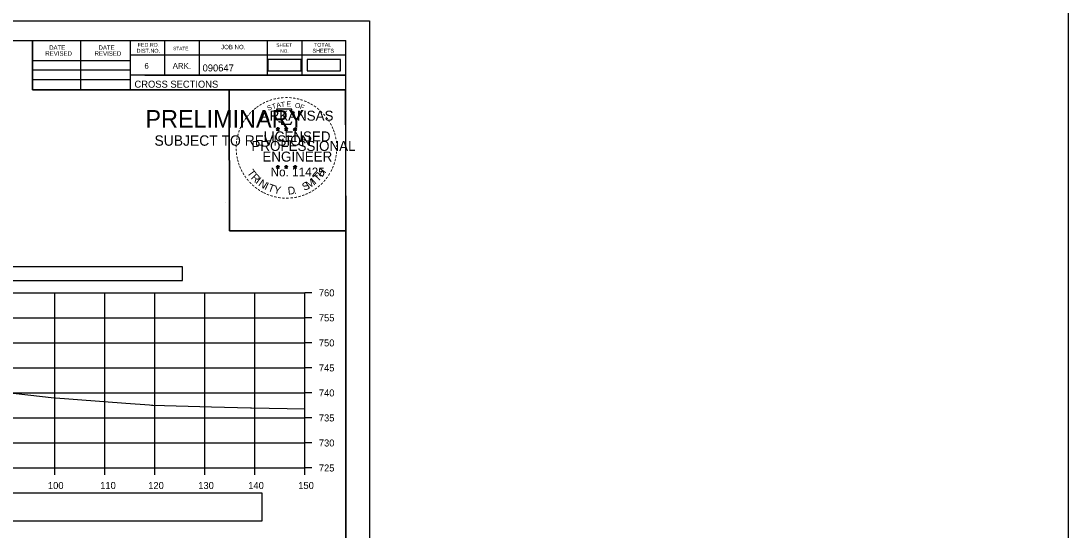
# Model space of a CAD drawing. Extents: x 1202951 to 1376887, y 378065 to 728038.
# Drawn here: x 1376677.9 to 1376887.3, y 378519.4 to 378621.2 of the extents above; entities that cross this region are included whole.
import ezdxf

# ---------------------------------------------------------------- set-up
doc = ezdxf.new("R2010")
doc.units = 0
for name, color, linetype in [('Default', 7, 'Continuous'), ('R_Alt Surface', 7, 'Continuous'), ('R_Axis', 7, 'Continuous'), ('R_Axis Annot', 7, 'Continuous'), ('R_Border', 7, 'Continuous'), ('R_Border PE', 7, 'Continuous'), ('R_Border Prem', 7, 'Continuous'), ('R_Exist Surface', 7, 'Continuous'), ('R_Grid', 7, 'Continuous'), ('R_No Plot', 7, 'Continuous')]:
    doc.layers.add(name, color=color, linetype=linetype)

msp = doc.modelspace()

# ---------------------------------------------------------------- linework, layer by layer
at = {"layer": 'Default'}
msp.add_lwpolyline([(1376735.11, 378611.18), (1376741.79, 378611.18), (1376741.79, 378613.49), (1376735.11, 378613.49)], close=True, dxfattribs=at)
at = {"layer": 'R_Alt Surface'}
for points in [[(1376727.24, 378611.18), (1376733.92, 378611.18), (1376733.92, 378613.49), (1376727.24, 378613.49)], [(1376434.67, 378569.32), (1376710.2, 378569.32), (1376710.2, 378572.02), (1376434.67, 378572.02)], [(1376615.43, 378521.29), (1376726.14, 378521.29), (1376726.14, 378526.82), (1376615.43, 378526.82)]]:
    msp.add_lwpolyline(points, close=True, dxfattribs=at)
at = {"layer": 'R_Axis'}
for p, q in [((1376734.67, 378531.82), (1376734.67, 378566.82)), ((1376736.07, 378566.82), (1376734.67, 378566.82)), ((1376736.07, 378561.82), (1376734.67, 378561.82)), ((1376736.07, 378556.82), (1376734.67, 378556.82)), ((1376736.07, 378551.82), (1376734.67, 378551.82)), ((1376736.07, 378546.82), (1376734.67, 378546.82)), ((1376736.07, 378541.82), (1376734.67, 378541.82)), ((1376736.07, 378536.82), (1376734.67, 378536.82)), ((1376434.67, 378531.82), (1376734.67, 378531.82)), ((1376684.67, 378530.42), (1376684.67, 378531.82)), ((1376694.67, 378530.42), (1376694.67, 378531.82)), ((1376704.67, 378530.42), (1376704.67, 378531.82)), ((1376714.67, 378530.42), (1376714.67, 378531.82)), ((1376724.67, 378530.42), (1376724.67, 378531.82)), ((1376734.67, 378530.42), (1376734.67, 378531.82)), ((1376736.07, 378531.82), (1376734.67, 378531.82))]:
    msp.add_line(p, q, dxfattribs=at)
at = {"layer": 'R_Border'}
for p, q in [((1376426.67, 378617.28), (1376742.85, 378617.28)), ((1376680.21, 378607.4), (1376680.21, 378617.28)), ((1376689.89, 378607.4), (1376689.89, 378617.28)), ((1376699.75, 378617.28), (1376699.75, 378607.4)), ((1376706.59, 378617.28), (1376706.59, 378610.34)), ((1376713.53, 378617.28), (1376713.53, 378610.34)), ((1376727.11, 378617.28), (1376727.11, 378610.34)), ((1376734.05, 378617.28), (1376734.05, 378610.34)), ((1376742.85, 378411.82), (1376742.85, 378617.28)), ((1376742.85, 378614.34), (1376699.75, 378614.34)), ((1376742.85, 378614.36), (1376742.85, 378614.36)), ((1376680.21, 378613.26), (1376699.75, 378613.26)), ((1376680.21, 378611.4), (1376699.75, 378611.4)), ((1376680.21, 378609.46), (1376699.75, 378609.46)), ((1376742.85, 378610.34), (1376699.75, 378610.34)), ((1376702.71, 378610.34), (1376742.85, 378610.34)), ((1376742.85, 378607.4), (1376680.21, 378607.4))]:
    msp.add_line(p, q, dxfattribs=at)
at = {"layer": 'R_Border PE'}
for p, q in [((1376728.94, 378599.65), (1376729.28, 378599.54)), ((1376728.94, 378599.65), (1376729.19, 378599.61)), ((1376728.94, 378599.65), (1376729.17, 378599.53)), ((1376729.07, 378599.24), (1376729.28, 378599.54)), ((1376729.07, 378599.24), (1376729.19, 378599.49)), ((1376729.07, 378599.24), (1376729.28, 378599.46)), ((1376729.28, 378599.91), (1376729.24, 378599.65)), ((1376729.28, 378599.54), (1376729.28, 378599.91)), ((1376729.28, 378599.91), (1376729.33, 378599.66)), ((1376729.63, 378599.65), (1376729.28, 378599.54)), ((1376729.5, 378599.24), (1376729.28, 378599.54)), ((1376729.5, 378599.24), (1376729.28, 378599.46)), ((1376729.63, 378599.65), (1376729.35, 378599.6)), ((1376729.5, 378599.24), (1376729.36, 378599.53)), ((1376729.63, 378599.65), (1376729.43, 378599.55)), ((1376730.61, 378599.65), (1376730.95, 378599.54)), ((1376730.61, 378599.65), (1376730.86, 378599.61)), ((1376730.61, 378599.65), (1376730.84, 378599.53)), ((1376730.74, 378599.24), (1376730.95, 378599.54)), ((1376730.74, 378599.24), (1376730.86, 378599.49)), ((1376730.74, 378599.24), (1376730.95, 378599.46)), ((1376730.95, 378599.91), (1376730.91, 378599.65)), ((1376730.95, 378599.54), (1376730.95, 378599.91)), ((1376730.95, 378599.91), (1376731, 378599.66)), ((1376731.3, 378599.65), (1376730.95, 378599.54)), ((1376731.17, 378599.24), (1376730.95, 378599.54)), ((1376731.17, 378599.24), (1376730.95, 378599.46)), ((1376731.3, 378599.65), (1376731.02, 378599.6)), ((1376731.17, 378599.24), (1376731.03, 378599.53)), ((1376731.3, 378599.65), (1376731.1, 378599.55)), ((1376732.37, 378599.64), (1376732.72, 378599.53)), ((1376732.37, 378599.64), (1376732.62, 378599.59)), ((1376732.37, 378599.64), (1376732.61, 378599.52)), ((1376732.5, 378599.23), (1376732.72, 378599.53)), ((1376732.5, 378599.23), (1376732.63, 378599.48)), ((1376732.5, 378599.23), (1376732.72, 378599.45)), ((1376732.72, 378599.89), (1376732.68, 378599.64)), ((1376732.72, 378599.53), (1376732.72, 378599.89)), ((1376732.72, 378599.89), (1376732.77, 378599.64)), ((1376733.07, 378599.64), (1376732.72, 378599.53)), ((1376732.93, 378599.23), (1376732.72, 378599.53)), ((1376732.93, 378599.23), (1376732.72, 378599.45)), ((1376733.07, 378599.64), (1376732.78, 378599.59)), ((1376732.93, 378599.23), (1376732.79, 378599.52)), ((1376733.07, 378599.64), (1376732.86, 378599.54)), ((1376728.93, 378592.08), (1376729.28, 378591.97)), ((1376728.93, 378592.08), (1376729.18, 378592.03)), ((1376728.93, 378592.08), (1376729.17, 378591.96)), ((1376729.06, 378591.67), (1376729.28, 378591.97)), ((1376729.06, 378591.67), (1376729.19, 378591.91)), ((1376729.06, 378591.67), (1376729.28, 378591.89)), ((1376729.28, 378592.33), (1376729.24, 378592.08)), ((1376729.28, 378591.97), (1376729.28, 378592.33)), ((1376729.28, 378592.33), (1376729.33, 378592.08)), ((1376729.63, 378592.08), (1376729.28, 378591.97)), ((1376729.49, 378591.67), (1376729.28, 378591.97)), ((1376729.49, 378591.67), (1376729.28, 378591.88)), ((1376729.63, 378592.08), (1376729.34, 378592.03)), ((1376729.49, 378591.67), (1376729.36, 378591.96)), ((1376729.63, 378592.08), (1376729.42, 378591.98)), ((1376730.6, 378592.08), (1376730.95, 378591.97)), ((1376730.6, 378592.08), (1376730.85, 378592.03)), ((1376730.6, 378592.08), (1376730.84, 378591.96)), ((1376730.73, 378591.67), (1376730.95, 378591.97)), ((1376730.73, 378591.67), (1376730.86, 378591.91)), ((1376730.73, 378591.67), (1376730.95, 378591.89)), ((1376730.95, 378592.33), (1376730.91, 378592.08)), ((1376730.95, 378591.97), (1376730.95, 378592.33)), ((1376730.95, 378592.33), (1376731, 378592.08)), ((1376731.3, 378592.08), (1376730.95, 378591.97)), ((1376731.16, 378591.67), (1376730.95, 378591.97)), ((1376731.16, 378591.67), (1376730.95, 378591.88)), ((1376731.3, 378592.08), (1376731.01, 378592.03)), ((1376731.16, 378591.67), (1376731.03, 378591.96)), ((1376731.3, 378592.08), (1376731.09, 378591.98)), ((1376732.37, 378592.07), (1376732.72, 378591.96)), ((1376732.37, 378592.07), (1376732.62, 378592.02)), ((1376732.37, 378592.07), (1376732.6, 378591.95)), ((1376732.5, 378591.66), (1376732.72, 378591.96)), ((1376732.5, 378591.66), (1376732.63, 378591.9)), ((1376732.5, 378591.66), (1376732.71, 378591.88)), ((1376732.72, 378592.32), (1376732.68, 378592.07)), ((1376732.93, 378591.66), (1376732.71, 378591.87)), ((1376732.72, 378591.96), (1376732.72, 378592.32)), ((1376732.72, 378592.32), (1376732.77, 378592.07)), ((1376733.06, 378592.07), (1376732.72, 378591.96)), ((1376732.93, 378591.66), (1376732.72, 378591.96)), ((1376733.06, 378592.07), (1376732.78, 378592.02)), ((1376732.93, 378591.66), (1376732.79, 378591.95)), ((1376733.06, 378592.07), (1376732.86, 378591.97))]:
    msp.add_line(p, q, dxfattribs=at)
for points in [[(1376728.98, 378603.53), (1376729.25, 378602.7)], [(1376732.49, 378602.61), (1376732.63, 378602.89), (1376731.94, 378602.87), (1376732.09, 378603.53), (1376728.98, 378603.53)], [(1376729.47, 378601.11), (1376729.47, 378601.02), (1376730.03, 378601), (1376729.98, 378600.53), (1376731.85, 378600.53), (1376732.05, 378601.06)], [(1376729.28, 378599.91), (1376729.5, 378599.24), (1376728.94, 378599.65), (1376729.63, 378599.65), (1376729.07, 378599.24), (1376729.28, 378599.91)], [(1376730.95, 378599.91), (1376731.17, 378599.24), (1376730.61, 378599.65), (1376731.3, 378599.65), (1376730.74, 378599.24), (1376730.95, 378599.91)], [(1376732.72, 378599.89), (1376732.93, 378599.23), (1376732.37, 378599.64), (1376733.07, 378599.64), (1376732.5, 378599.23), (1376732.72, 378599.89)], [(1376729.28, 378592.33), (1376729.49, 378591.67), (1376728.93, 378592.08), (1376729.63, 378592.08), (1376729.06, 378591.67), (1376729.28, 378592.33)], [(1376730.95, 378592.33), (1376731.16, 378591.67), (1376730.6, 378592.08), (1376731.3, 378592.08), (1376730.73, 378591.67), (1376730.95, 378592.33)], [(1376732.72, 378592.32), (1376732.93, 378591.66), (1376732.37, 378592.07), (1376733.06, 378592.07), (1376732.5, 378591.66), (1376732.72, 378592.32)]]:
    msp.add_lwpolyline(points, dxfattribs=at)
for centre, radius in [((1376729.28, 378599.54), 0.172), ((1376729.28, 378599.54), 0.145), ((1376729.28, 378599.54), 0.116), ((1376729.28, 378599.54), 0.0991), ((1376729.28, 378599.54), 0.0747), ((1376729.28, 378599.54), 0.0495), ((1376729.28, 378599.54), 0.0296), ((1376730.95, 378599.54), 0.172), ((1376730.95, 378599.54), 0.145), ((1376730.95, 378599.54), 0.116), ((1376730.95, 378599.54), 0.0991), ((1376730.95, 378599.54), 0.0747), ((1376730.95, 378599.54), 0.0495), ((1376730.95, 378599.54), 0.0296), ((1376732.72, 378599.53), 0.172), ((1376732.72, 378599.53), 0.145), ((1376732.72, 378599.53), 0.116), ((1376732.72, 378599.53), 0.0991), ((1376732.72, 378599.53), 0.0747), ((1376732.72, 378599.53), 0.0495), ((1376732.72, 378599.53), 0.0296), ((1376729.28, 378591.97), 0.172), ((1376729.28, 378591.97), 0.145), ((1376729.28, 378591.97), 0.116), ((1376729.28, 378591.97), 0.0991), ((1376729.28, 378591.97), 0.0747), ((1376729.28, 378591.97), 0.0495), ((1376729.28, 378591.97), 0.0296), ((1376730.95, 378591.97), 0.172), ((1376730.95, 378591.97), 0.145), ((1376730.95, 378591.97), 0.116), ((1376730.95, 378591.97), 0.0991), ((1376730.95, 378591.97), 0.0747), ((1376730.95, 378591.97), 0.0495), ((1376730.95, 378591.97), 0.0296), ((1376732.72, 378591.96), 0.172), ((1376732.72, 378591.96), 0.145), ((1376732.72, 378591.96), 0.116), ((1376732.72, 378591.96), 0.0991), ((1376732.72, 378591.96), 0.0747), ((1376732.72, 378591.96), 0.0495), ((1376732.72, 378591.96), 0.0296)]:
    msp.add_circle(centre, radius, dxfattribs=at)
at = {"layer": 'R_Exist Surface'}
msp.add_lwpolyline([(1376663.94, 378548.16), (1376682.2, 378546.14), (1376683.97, 378545.91), (1376698.86, 378544.76), (1376703.59, 378544.41), (1376704, 378544.38), (1376704.27, 378544.37), (1376716.02, 378544.06), (1376723.79, 378543.85), (1376724.03, 378543.85), (1376734.67, 378543.65)], dxfattribs=at)
at = {"layer": 'R_Grid'}
for p, q in [((1376434.67, 378566.82), (1376734.67, 378566.82)), ((1376684.67, 378531.82), (1376684.67, 378566.82)), ((1376694.67, 378531.82), (1376694.67, 378566.82)), ((1376704.67, 378531.82), (1376704.67, 378566.82)), ((1376714.67, 378531.82), (1376714.67, 378566.82)), ((1376724.67, 378531.82), (1376724.67, 378566.82)), ((1376734.67, 378531.82), (1376734.67, 378566.82)), ((1376434.67, 378561.82), (1376734.67, 378561.82)), ((1376434.67, 378556.82), (1376734.67, 378556.82)), ((1376434.67, 378551.82), (1376734.67, 378551.82)), ((1376434.67, 378546.82), (1376734.67, 378546.82)), ((1376434.67, 378541.82), (1376734.67, 378541.82)), ((1376434.67, 378536.82), (1376734.67, 378536.82)), ((1376434.67, 378531.82), (1376734.67, 378531.82))]:
    msp.add_line(p, q, dxfattribs=at)
at = {"layer": 'R_No Plot'}
for p, q in [((1376414.27, 378621.17), (1376747.6, 378621.17)), ((1376718.89, 378584.94), (1376718.89, 378584.94))]:
    msp.add_line(p, q, dxfattribs=at)
for points in [[(1376303.24, 380162.87), (1376887.29, 380162.87), (1376887.29, 378065.39), (1376303.24, 378065.39)], [(1376414.26, 378621.17), (1376747.6, 378621.17), (1376747.6, 378407.83), (1376414.26, 378407.83)], [(1376660.59, 378617.28), (1376680.21, 378617.28), (1376680.21, 378607.4), (1376696.32, 378607.4), (1376719.52, 378607.4), (1376719.64, 378579.24), (1376742.85, 378579.24), (1376742.85, 378411.82), (1376426.67, 378411.82), (1376426.67, 378617.28)], [(1376719.52, 378607.4), (1376742.73, 378607.4), (1376742.85, 378579.24), (1376719.64, 378579.24)]]:
    msp.add_lwpolyline(points, close=True, dxfattribs=at)

# ---------------------------------------------------------------- texts
at = {"layer": 'R_Axis Annot'}
for s, p in [('760', (1376737.47, 378566.12)), ('755', (1376737.47, 378561.12)), ('750', (1376737.47, 378556.12)), ('745', (1376737.47, 378551.12)), ('740', (1376737.47, 378546.12)), ('735', (1376737.47, 378541.12)), ('730', (1376737.47, 378536.12)), ('725', (1376737.47, 378531.12)), ('100', (1376683.3, 378527.62)), ('110', (1376693.75, 378527.62)), ('120', (1376703.35, 378527.62)), ('130', (1376713.35, 378527.62)), ('140', (1376723.35, 378527.62)), ('150', (1376733.35, 378527.62))]:
    msp.add_text(s, height=1.4, dxfattribs=at).set_placement(p)
at = {"layer": 'R_Border'}
for s, height, p in [('DATE', 0.879, (1376683.55, 378615.41)), ('DATE', 0.879, (1376693.41, 378615.41)), ('DIST.NO.', 0.782, (1376701.03, 378614.82)), ('FED.RD.', 0.782, (1376701.23, 378616)), ('STATE', 0.684, (1376708.35, 378615.32)), ('JOB NO.', 0.879, (1376717.93, 378615.52)), ('SHEET', 0.684, (1376728.97, 378616)), ('NO.', 0.684, (1376729.75, 378614.82)), ('SHEETS', 0.782, (1376736.21, 378614.82)), ('TOTAL', 0.782, (1376736.49, 378616)), ('REVISED', 0.879, (1376682.77, 378614.23)), ('REVISED', 0.879, (1376692.63, 378614.23)), ('6', 1.17, (1376702.59, 378611.6)), ('ARK.', 1.172, (1376708.25, 378611.6)), ('090647', 1.4, (1376714.23, 378611.08)), ('CROSS SECTIONS', 1.4, (1376700.61, 378607.83))]:
    msp.add_text(s, height=height, rotation=360, dxfattribs=at).set_placement(p)
at = {"layer": 'R_Border PE'}
for s, height, rotation, p in [('-', 1.6, 28.7918, (1376726.46, 378604.07)), ('-', 1.6, 24.3072, (1376727.09, 378604.39)), ('-', 1.6, 19.1761, (1376727.72, 378604.66)), ('-', 1.6, 13.6301, (1376728.47, 378604.9)), ('-', 1.6, 10.2193, (1376729.15, 378605.06)), ('T', 1, 6.0228, (1376729.92, 378603.96)), ('-', 1.6, 5.8968, (1376729.88, 378605.17)), ('-', 1.6, 0.1862, (1376730.65, 378605.24)), ('E', 1, 0.8323, (1376731.03, 378604.07)), ('-', 1.6, 357.743, (1376731.38, 378605.23)), ('-', 1.6, 352.1617, (1376732.12, 378605.17)), ('-', 1.6, 347.2049, (1376732.84, 378605.06)), ('-', 1.6, 342.3362, (1376733.47, 378604.9)), ('-', 1.6, 337.8551, (1376734.21, 378604.68)), ('-', 1.6, 334.1211, (1376734.84, 378604.41)), ('-', 1.6, 48.423, (1376723.93, 378602.03)), ('-', 1.6, 42.9622, (1376724.37, 378602.51)), ('-', 1.6, 38.9507, (1376724.81, 378602.93)), ('-', 1.6, 36.2317, (1376725.28, 378603.31)), ('-', 1.6, 34.0636, (1376725.86, 378603.7)), ('ARKANSAS', 2, 360, (1376725.83, 378601.24)), ('S', 1, 21.594, (1376727.33, 378603.21)), ('T', 1, 16.4036, (1376728.25, 378603.54)), ('A', 1, 11.2132, (1376729.07, 378603.79)), ('O', 1, 350.4515, (1376732.63, 378603.86)), ('F', 1, 340.0707, (1376733.58, 378603.63)), ('-', 1.6, 329.6409, (1376735.42, 378604.13)), ('-', 1.6, 325.8627, (1376736.06, 378603.77)), ('-', 1.6, 320.5297, (1376736.67, 378603.34)), ('-', 1.6, 315.5786, (1376737.27, 378602.85)), ('-', 1.6, 58.0706, (1376722.78, 378600.45)), ('-', 1.6, 54.2325, (1376723.11, 378600.98)), ('-', 1.6, 50.6142, (1376723.52, 378601.55)), ('-', 1.6, 309.8797, (1376737.84, 378602.3)), ('-', 1.6, 306.6522, (1376738.37, 378601.7)), ('-', 1.4, 303.6753, (1376738.85, 378601.13)), ('-', 1.6, 299.6684, (1376739.17, 378600.52)), ('-', 1.6, 72.3945, (1376721.99, 378598.6)), ('-', 1.6, 67.7743, (1376722.21, 378599.23)), ('-', 1.6, 62.8713, (1376722.47, 378599.84)), ('LICENSED', 2, 360, (1376726.43, 378597.09)), ('DWB', 0.01, 360, (1376729.27, 378599.54)), ('DWB', 0.01, 360, (1376730.94, 378599.54)), ('DWB', 0.01, 360, (1376732.71, 378599.52)), ('-', 1.6, 294.6628, (1376739.49, 378599.91)), ('-', 1.6, 290.5728, (1376739.75, 378599.34)), ('-', 1.6, 285.1233, (1376739.99, 378598.76)), ('-', 1.6, 85.1863, (1376721.59, 378596.48)), ('-', 1.6, 81.2013, (1376721.66, 378597.17)), ('-', 1.6, 75.461, (1376721.8, 378597.88)), ('PROFESSIONAL', 2, 360, (1376724, 378595.19)), ('-', 1.6, 280.5493, (1376740.19, 378598.01)), ('-', 1.6, 276.5962, (1376740.35, 378597.25)), ('-', 1.6, 94.1959, (1376721.6, 378595.05)), ('-', 1.6, 89.0622, (1376721.56, 378595.78)), ('-', 1.6, 98.9479, (1376721.67, 378594.39)), ('ENGINEER', 2, 360, (1376726.19, 378593.06)), ('-', 1.6, 263.5172, (1376740.42, 378595.23)), ('-', 1.6, 274.3301, (1376740.41, 378596.52)), ('-', 1.6, 269.9407, (1376740.44, 378595.89)), ('-', 1.6, 101.7149, (1376721.81, 378593.65)), ('-', 1.6, 105.4578, (1376721.97, 378593.06)), ('-', 1.6, 109.0874, (1376722.18, 378592.43)), ('-', 1.6, 252.8681, (1376740.06, 378593.17)), ('-', 1.6, 255.7626, (1376740.24, 378593.89)), ('-', 1.6, 260.9953, (1376740.35, 378594.57)), ('-', 1.6, 114.0643, (1376722.44, 378591.83)), ('-', 1.6, 115.7289, (1376722.74, 378591.21)), ('-', 1.6, 120.4471, (1376723.1, 378590.63)), ('T', 1.54, 306.0406, (1376723.04, 378590.81)), ('R', 1.54, 314.005, (1376723.8, 378589.76)), ('No. 11425', 1.757, 360, (1376727.82, 378590.11)), ('DWB', 0.01, 360, (1376729.27, 378591.96)), ('DWB', 0.01, 360, (1376730.94, 378591.96)), ('DWB', 0.01, 360, (1376732.7, 378591.95)), ('T', 1.54, 46.6444, (1376737.27, 378588.9)), ('H', 1.54, 54.6088, (1376738.16, 378589.84)), ('-', 1.6, 239.0712, (1376739.18, 378591.12)), ('-', 1.6, 244.6197, (1376739.58, 378591.87)), ('-', 1.6, 247.8887, (1376739.84, 378592.5)), ('-', 1.6, 125.8934, (1376723.5, 378590.07)), ('-', 1.6, 130.7181, (1376723.96, 378589.51)), ('-', 1.6, 134.2238, (1376724.48, 378588.97)), ('-', 1.6, 138.9338, (1376725.01, 378588.51)), ('I', 1.54, 321.9694, (1376724.7, 378588.83)), ('N', 1.54, 326.5002, (1376725.27, 378588.35)), ('I', 1.54, 335.3603, (1376726.48, 378587.57)), ('T', 1.54, 339.8912, (1376727.14, 378587.24)), ('Y', 1.54, 347.8556, (1376728.36, 378586.8)), ('S', 1.54, 26.9312, (1376734.59, 378587.17)), ('M', 1.54, 32.6563, (1376735.43, 378587.57)), ('I', 1.54, 42.1136, (1376736.71, 378588.42)), ('-', 1.6, 221.0851, (1376737.35, 378588.83)), ('-', 1.6, 225.7653, (1376737.87, 378589.34)), ('-', 1.6, 231.2538, (1376738.35, 378589.9)), ('-', 1.6, 233.8452, (1376738.78, 378590.47)), ('-', 1.6, 144.6463, (1376725.56, 378588.1)), ('-', 1.6, 148.0898, (1376726.12, 378587.73)), ('-', 1.6, 151.5704, (1376726.7, 378587.4)), ('-', 1.6, 154.6002, (1376727.22, 378587.16)), ('-', 1.6, 158.5612, (1376727.85, 378586.9)), ('-', 1.6, 162.7983, (1376728.53, 378586.69)), ('-', 1.6, 167.5555, (1376729.25, 378586.53)), ('D', 1.54, 6.3969, (1376731.34, 378586.44)), ('.', 1.54, 13.7642, (1376732.53, 378586.56)), ('-', 1.6, 195.4743, (1376733.79, 378586.79)), ('-', 1.6, 200.7184, (1376734.46, 378587.03)), ('-', 1.6, 204.2516, (1376735.08, 378587.3)), ('-', 1.6, 207.3568, (1376735.71, 378587.62)), ('-', 1.6, 212.2491, (1376736.27, 378587.97)), ('-', 1.6, 215.7363, (1376736.8, 378588.36)), ('-', 1.6, 173.1155, (1376730.02, 378586.42)), ('-', 1.6, 176.5183, (1376730.77, 378586.36)), ('-', 1.6, 181.5918, (1376731.51, 378586.38)), ('-', 1.6, 185.8167, (1376732.32, 378586.46)), ('-', 1.6, 191.2858, (1376733.06, 378586.59))]:
    msp.add_text(s, height=height, rotation=rotation, dxfattribs=at).set_placement(p)
at = {"layer": 'R_Border Prem'}
for s, height, p in [('PRELIMINARY', 3.5, (1376702.8, 378599.86)), ('DWB', 0.01, (1376703.55, 378601.71)), ('SUBJECT TO REVISION', 2.0751, (1376704.61, 378596.23))]:
    msp.add_text(s, height=height, rotation=360, dxfattribs=at).set_placement(p)

doc.saveas('drawing.dxf')
